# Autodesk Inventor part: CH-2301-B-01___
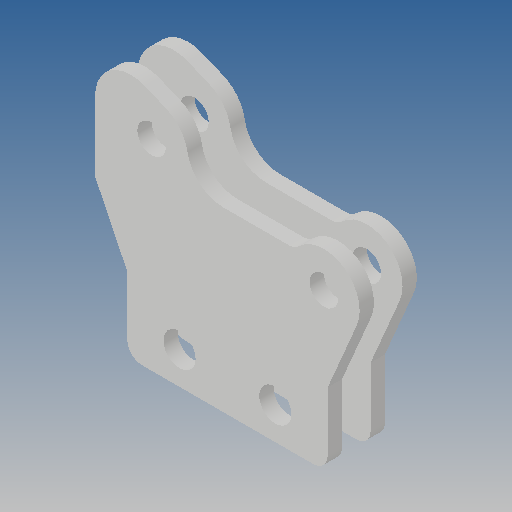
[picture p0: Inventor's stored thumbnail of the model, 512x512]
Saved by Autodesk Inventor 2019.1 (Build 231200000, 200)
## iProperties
Created: 2012-09
Part Number: CH-2301-B-01___
Material: Ogólny
Document SubType Name: Modeling
Designer: CADENGINEERING4
Density: 1 g/cm^3
Appearance: Domyślna
Author: CADENGINEERING4
Revision Number: ÈÎºÎ
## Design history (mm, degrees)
feature "NONE" [ÊäÈë]
feature "ÊäÈë2"
node "Bryła1"
node "Bryła2"
